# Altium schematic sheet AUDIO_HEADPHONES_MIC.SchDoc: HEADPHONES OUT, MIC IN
size A4; Author: Silvio Navaretti; CompanyName: Arduino SRL; DrawnBy: Silvio Navaretti; Engineer: Silvio Navaretti; Organization: Arduino SRL; DocumentNumber: ASX00083; SheetNumber: 8; SheetTotal: 11; RevAuthor: Silvio Navaretti
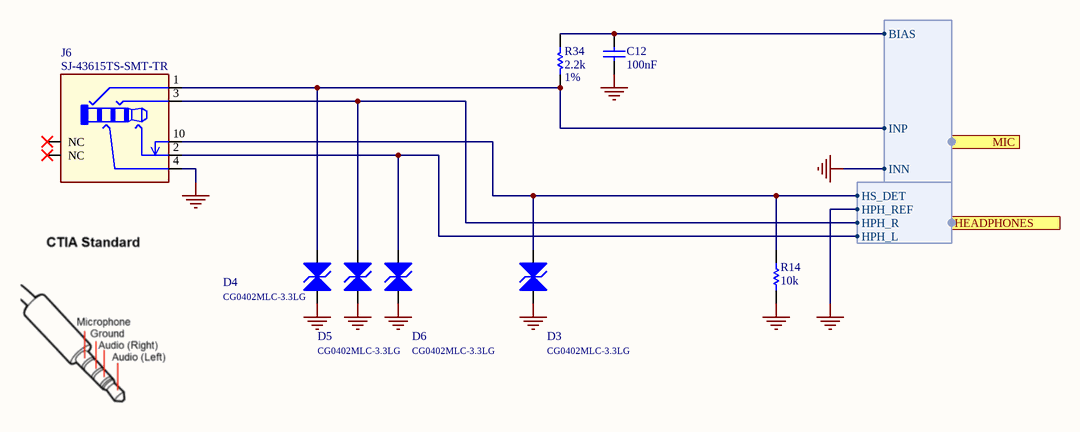
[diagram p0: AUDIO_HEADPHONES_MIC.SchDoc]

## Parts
C12  value 100nF  [CAP-0402]  (hidden comment: GRM155R61H104KE19D)
D3  CG0402MLC-3.3LG  [0402]
D4  CG0402MLC-3.3LG  [0402]
D5  CG0402MLC-3.3LG  [0402]
D6  CG0402MLC-3.3LG  [0402]
J6  SJ-43615TS-SMT-TR  [SJ-43615TS-SMT-TR]
R14  value 10k  [RES-0402]  (hidden comment: CRCW040210K0FKED)
R34  value 2.2k  Tolerance: 1%  [RES-0402]  (hidden comment: AF0402FR-072K2L)

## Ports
HEADPHONES (harness HEADPHONES), MIC (harness MIC)

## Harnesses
MIC: INP, INN, BIAS
HEADPHONES: HPH_L, HPH_R, HPH_REF, HS_DET

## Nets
GND: C12.1 D3.A D4.A D5.A D6.A J6.4 R14.1 ; port MIC.INN, port HEADPHONES.HPH_REF
NetC12_2: C12.2 R34.1 ; port MIC.BIAS
NetD3_C: D3.C J6.10 R14.2 ; port HEADPHONES.HS_DET
NetD4_C: D4.C J6.1 R34.2 ; port MIC.INP
NetD5_C: D5.C J6.3 ; port HEADPHONES.HPH_R
NetD6_C: D6.C J6.2 ; port HEADPHONES.HPH_L

Not connected (* = marked no-connect by the designer): J6 11(NC)* 12(NC)*

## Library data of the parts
C12 = C0015-A.14: CAP CHIP 0402 100nF 10% 50V X5R; Manufacturer: Murata; Code Arduino: A5141
D3-D6 = D0073-A.3: DIODE TVS SMD 0402 3.3V ESD PROTECTION; Manufacturer: Bourns; Code Arduino: D0073; Direction: Bidirectional
J6 = J0533-A.9: CONN Audio Jack 3.5mm, 4 conductor, tip switch, SMD mid mount; Manufacturer: Same Sky; Code Arduino: J0533
R14 = R0003-A.24: RES CHIP 0402 10k 1% 1/16W; Manufacturer: Vishay; Code Arduino: 0136; Power: 62.5mW; Temperature coefficient: 100ppm
R34 = R0286-A.3: RES CHIP 0402 2k2 1% 1/16W; Manufacturer: Yageo; Temperature coefficient: 100ppm; Power: 62.5mW; Code Arduino: R0286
